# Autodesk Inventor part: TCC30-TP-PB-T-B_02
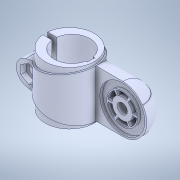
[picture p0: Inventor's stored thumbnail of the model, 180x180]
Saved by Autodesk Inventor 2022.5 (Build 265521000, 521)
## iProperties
Created: 2023-09
Part Number: TCC30-TP-PB-T-B_02
Material: 一般
Document SubType Name: Modeling
Designer: ImaoCorp
Density: 1 g/cm^3
Appearance: 既定
Author: ImaoCorp
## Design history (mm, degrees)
feature "TCC30-TP-PB-T-B_02"
node "ソリッド1"
